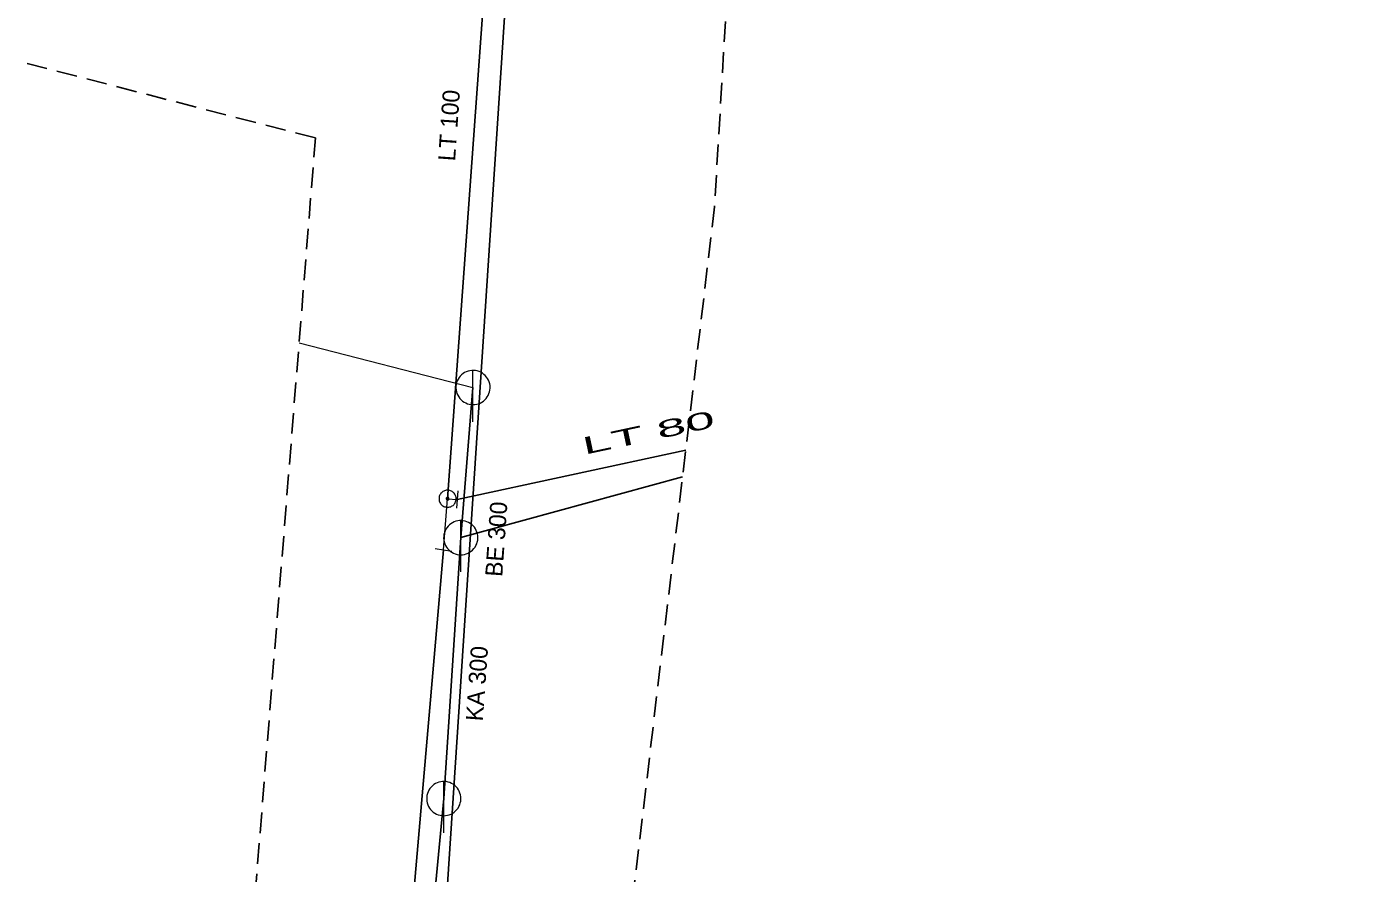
# Model space of a CAD drawing. Extents: x -686636 to -686482, y -972667 to -972167.
# Drawn here: x -686559.3 to -686482.1, y -972617.8 to -972568.3 of the extents above; entities that cross this region are included whole.
import ezdxf

# ---------------------------------------------------------------- set-up
doc = ezdxf.new("R2010")
doc.units = 0
doc.header["$LTSCALE"] = 0.4
doc.linetypes.add('MEDIUM_DASHED', pattern=[4.5, 3, -1.5])
for name, color, linetype, lineweight in [('1', 7, 'MEDIUM_DASHED', 25), ('11', 7, 'Continuous', 13), ('14', 7, 'Continuous', 25), ('17', 7, 'Continuous', 25), ('22', 7, 'Continuous', 13), ('34', 7, 'Continuous', 13), ('47', 7, 'Continuous', 13)]:
    doc.layers.add(name, color=color, linetype=linetype, lineweight=lineweight)

msp = doc.modelspace()

# ---------------------------------------------------------------- linework, layer by layer
at = {"layer": '1'}
msp.add_lwpolyline([(-686523.086, -972200.227), (-686492.539, -972167.269), (-686482.089, -972185.758), (-686542.379, -972270.164), (-686548.006, -972279.81), (-686543.183, -972295.084), (-686523.086, -972321.612), (-686521.478, -972360.197), (-686540.771, -972442.192), (-686521.478, -972473.543), (-686515.047, -972510.521), (-686519.067, -972578.85), (-686529.517, -972667.276), (-686549.614, -972665.668), (-686542.379, -972574.831), (-686589.003, -972562.773), (-686636.432, -972544.284), (-686625.981, -972525.795), (-686541.575, -972549.911), (-686539.967, -972501.678), (-686569.711, -972440.584), (-686549.614, -972329.65), (-686564.887, -972297.496), (-686572.926, -972277.399)], close=True, dxfattribs=at)
at = {"layer": '11'}
msp.add_line((-686543.332, -972586.796), (-686533.176, -972589.405), dxfattribs=at)
at = {"layer": '14'}
for p, q in [((-686533.176, -972589.405), (-686533.89, -972598.176)), ((-686520.931, -972594.627), (-686533.89, -972598.176)), ((-686533.89, -972598.176), (-686534.882, -972613.416)), ((-686534.882, -972613.416), (-686537.964, -972646.203))]:
    msp.add_line(p, q, dxfattribs=at)
at = {"layer": '14', "lineweight": 13}
for p, q in [((-686534.899, -972598.886), (-686534.66, -972595.9)), ((-686534.66, -972595.9), (-686534.103, -972595.949))]:
    msp.add_line(p, q, dxfattribs=at)
at = {"layer": '14'}
msp.add_lwpolyline([(-686529.998, -972548.457), (-686530.171, -972549.975), (-686536.5, -972646.26)], dxfattribs=at)
at = {"layer": '17'}
for p, q in [((-686520.747, -972593.066), (-686534.103, -972595.949)), ((-686534.899, -972598.886), (-686539.43, -972651.21))]:
    msp.add_line(p, q, dxfattribs=at)
msp.add_lwpolyline([(-686531.079, -972544.64), (-686531.317, -972549.123), (-686531.386, -972550.671), (-686534.66, -972595.9)], dxfattribs=at)
at = {"layer": '22'}
for p, q in [((-686533.176, -972591.405), (-686533.175, -972588.405)), ((-686533.89, -972600.176), (-686533.889, -972597.176)), ((-686534.882, -972615.416), (-686534.881, -972612.416))]:
    msp.add_line(p, q, dxfattribs=at)
for points in [[(-686532.176, -972589.405), (-686532.181, -972589.296), (-686532.199, -972589.188), (-686532.229, -972589.082), (-686532.269, -972588.981), (-686532.321, -972588.884), (-686532.383, -972588.794), (-686532.455, -972588.711), (-686532.535, -972588.637), (-686532.623, -972588.571), (-686532.717, -972588.516), (-686532.817, -972588.471), (-686532.922, -972588.438), (-686533.029, -972588.416), (-686533.138, -972588.406), (-686533.248, -972588.408), (-686533.356, -972588.422), (-686533.463, -972588.447), (-686533.566, -972588.484), (-686533.664, -972588.533), (-686533.756, -972588.591), (-686533.842, -972588.66), (-686533.919, -972588.737), (-686533.988, -972588.823), (-686534.047, -972588.915), (-686534.095, -972589.013), (-686534.132, -972589.116), (-686534.158, -972589.223), (-686534.172, -972589.331), (-686534.175, -972589.441), (-686534.165, -972589.55), (-686534.144, -972589.657), (-686534.11, -972589.761), (-686534.066, -972589.861), (-686534.011, -972589.956), (-686533.945, -972590.044), (-686533.871, -972590.124), (-686533.788, -972590.196), (-686533.698, -972590.258), (-686533.602, -972590.31), (-686533.5, -972590.351), (-686533.395, -972590.381), (-686533.287, -972590.399), (-686533.177, -972590.405), (-686533.068, -972590.399), (-686532.96, -972590.381), (-686532.855, -972590.352), (-686532.753, -972590.311), (-686532.656, -972590.259), (-686532.566, -972590.197), (-686532.483, -972590.126), (-686532.408, -972590.046), (-686532.343, -972589.958), (-686532.287, -972589.864), (-686532.243, -972589.764), (-686532.209, -972589.66), (-686532.187, -972589.552), (-686532.177, -972589.443)], [(-686532.89, -972598.176), (-686532.895, -972598.067), (-686532.913, -972597.959), (-686532.943, -972597.853), (-686532.983, -972597.752), (-686533.035, -972597.655), (-686533.097, -972597.565), (-686533.169, -972597.482), (-686533.249, -972597.408), (-686533.337, -972597.342), (-686533.431, -972597.287), (-686533.531, -972597.242), (-686533.636, -972597.209), (-686533.743, -972597.187), (-686533.852, -972597.177), (-686533.962, -972597.179), (-686534.07, -972597.193), (-686534.177, -972597.218), (-686534.28, -972597.255), (-686534.378, -972597.304), (-686534.47, -972597.362), (-686534.556, -972597.431), (-686534.633, -972597.508), (-686534.702, -972597.594), (-686534.761, -972597.686), (-686534.809, -972597.784), (-686534.846, -972597.887), (-686534.872, -972597.994), (-686534.886, -972598.102), (-686534.889, -972598.212), (-686534.879, -972598.321), (-686534.858, -972598.428), (-686534.824, -972598.532), (-686534.78, -972598.632), (-686534.725, -972598.727), (-686534.659, -972598.815), (-686534.585, -972598.895), (-686534.502, -972598.967), (-686534.412, -972599.029), (-686534.316, -972599.081), (-686534.214, -972599.122), (-686534.109, -972599.152), (-686534.001, -972599.17), (-686533.891, -972599.176), (-686533.782, -972599.17), (-686533.674, -972599.152), (-686533.569, -972599.123), (-686533.467, -972599.082), (-686533.37, -972599.03), (-686533.28, -972598.968), (-686533.197, -972598.897), (-686533.122, -972598.817), (-686533.057, -972598.729), (-686533.001, -972598.635), (-686532.957, -972598.535), (-686532.923, -972598.431), (-686532.901, -972598.323), (-686532.891, -972598.214)], [(-686533.882, -972613.416), (-686533.887, -972613.307), (-686533.905, -972613.199), (-686533.935, -972613.093), (-686533.975, -972612.992), (-686534.027, -972612.895), (-686534.089, -972612.805), (-686534.161, -972612.722), (-686534.241, -972612.648), (-686534.329, -972612.582), (-686534.423, -972612.527), (-686534.523, -972612.482), (-686534.628, -972612.449), (-686534.735, -972612.427), (-686534.844, -972612.417), (-686534.954, -972612.419), (-686535.062, -972612.433), (-686535.169, -972612.458), (-686535.272, -972612.495), (-686535.37, -972612.544), (-686535.462, -972612.602), (-686535.548, -972612.671), (-686535.625, -972612.748), (-686535.694, -972612.834), (-686535.753, -972612.926), (-686535.801, -972613.024), (-686535.838, -972613.127), (-686535.864, -972613.234), (-686535.878, -972613.342), (-686535.881, -972613.452), (-686535.871, -972613.561), (-686535.85, -972613.668), (-686535.816, -972613.772), (-686535.772, -972613.872), (-686535.717, -972613.967), (-686535.651, -972614.055), (-686535.577, -972614.135), (-686535.494, -972614.207), (-686535.404, -972614.269), (-686535.308, -972614.321), (-686535.206, -972614.362), (-686535.101, -972614.392), (-686534.993, -972614.41), (-686534.883, -972614.416), (-686534.774, -972614.41), (-686534.666, -972614.392), (-686534.561, -972614.363), (-686534.459, -972614.322), (-686534.362, -972614.27), (-686534.272, -972614.208), (-686534.189, -972614.137), (-686534.114, -972614.057), (-686534.049, -972613.969), (-686533.993, -972613.875), (-686533.949, -972613.775), (-686533.915, -972613.671), (-686533.893, -972613.563), (-686533.883, -972613.454)]]:
    msp.add_lwpolyline(points, close=True, dxfattribs=at)
at = {"layer": '34'}
for p, q in [((-686534.059, -972595.45), (-686534.147, -972596.447)), ((-686535.393, -972598.81), (-686534.404, -972598.962))]:
    msp.add_line(p, q, dxfattribs=at)
at = {"layer": '47'}
for points in [[(-686534.635, -972595.4), (-686534.687, -972595.401), (-686534.739, -972595.406), (-686534.79, -972595.417), (-686534.84, -972595.433), (-686534.888, -972595.455), (-686534.933, -972595.482), (-686534.975, -972595.513), (-686535.014, -972595.548), (-686535.049, -972595.586), (-686535.08, -972595.628), (-686535.106, -972595.674), (-686535.126, -972595.722), (-686535.143, -972595.772), (-686535.153, -972595.823), (-686535.159, -972595.875), (-686535.158, -972595.927), (-686535.153, -972595.979), (-686535.142, -972596.031), (-686535.126, -972596.08), (-686535.104, -972596.128), (-686535.077, -972596.173), (-686535.047, -972596.216), (-686535.011, -972596.255), (-686534.973, -972596.29), (-686534.931, -972596.32), (-686534.885, -972596.346), (-686534.837, -972596.367), (-686534.787, -972596.383), (-686534.736, -972596.393), (-686534.684, -972596.399), (-686534.632, -972596.398), (-686534.58, -972596.393), (-686534.528, -972596.383), (-686534.479, -972596.366), (-686534.431, -972596.344), (-686534.386, -972596.318), (-686534.343, -972596.288), (-686534.304, -972596.252), (-686534.269, -972596.213), (-686534.239, -972596.171), (-686534.213, -972596.125), (-686534.192, -972596.078), (-686534.176, -972596.027), (-686534.166, -972595.976), (-686534.16, -972595.924), (-686534.161, -972595.872), (-686534.166, -972595.82), (-686534.176, -972595.769), (-686534.193, -972595.719), (-686534.215, -972595.671), (-686534.241, -972595.626), (-686534.272, -972595.584), (-686534.307, -972595.545), (-686534.346, -972595.51), (-686534.388, -972595.479), (-686534.434, -972595.453), (-686534.481, -972595.433), (-686534.532, -972595.416), (-686534.583, -972595.406)], [(-686534.655, -972595.818), (-686534.664, -972595.817), (-686534.673, -972595.819), (-686534.681, -972595.82), (-686534.689, -972595.823), (-686534.697, -972595.827), (-686534.704, -972595.831), (-686534.711, -972595.836), (-686534.718, -972595.842), (-686534.723, -972595.848), (-686534.728, -972595.855), (-686534.733, -972595.863), (-686534.736, -972595.871), (-686534.739, -972595.879), (-686534.741, -972595.886), (-686534.741, -972595.895), (-686534.742, -972595.904), (-686534.74, -972595.913), (-686534.739, -972595.921), (-686534.736, -972595.929), (-686534.732, -972595.937), (-686534.728, -972595.944), (-686534.723, -972595.951), (-686534.717, -972595.958), (-686534.711, -972595.964), (-686534.704, -972595.968), (-686534.696, -972595.973), (-686534.688, -972595.976), (-686534.68, -972595.979), (-686534.673, -972595.981), (-686534.664, -972595.981), (-686534.655, -972595.982), (-686534.646, -972595.98), (-686534.638, -972595.979), (-686534.63, -972595.976), (-686534.622, -972595.972), (-686534.615, -972595.969), (-686534.608, -972595.963), (-686534.601, -972595.957), (-686534.595, -972595.951), (-686534.591, -972595.944), (-686534.586, -972595.936), (-686534.583, -972595.928), (-686534.58, -972595.92), (-686534.578, -972595.913), (-686534.578, -972595.904), (-686534.577, -972595.895), (-686534.579, -972595.886), (-686534.58, -972595.878), (-686534.583, -972595.87), (-686534.587, -972595.862), (-686534.59, -972595.855), (-686534.596, -972595.848), (-686534.602, -972595.841), (-686534.608, -972595.836), (-686534.615, -972595.831), (-686534.623, -972595.826), (-686534.631, -972595.823), (-686534.639, -972595.82), (-686534.646, -972595.818)]]:
    msp.add_lwpolyline(points, close=True, dxfattribs=at)

# ---------------------------------------------------------------- texts
at = {"layer": '1'}
for s, p in [('LT 100', (-686534.222, -972576.207)), ('BE 300', (-686531.467, -972600.483)), ('KA 300', (-686532.599, -972608.919))]:
    msp.add_text(s, height=1, rotation=86, dxfattribs=at).set_placement(p)
at = {"layer": '1', "width": 2.3}
msp.add_text('LT 80 ', height=1, rotation=12, dxfattribs=at).set_placement((-686526.673, -972593.337))

doc.saveas('drawing.dxf')
